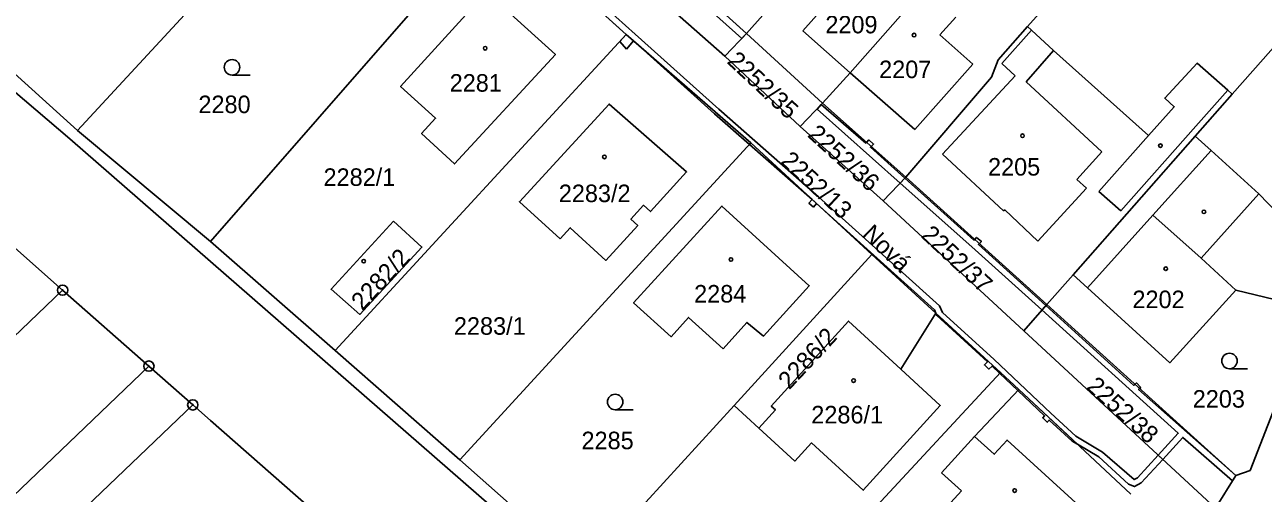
# Model space of a CAD drawing. Extents: x -562167 to -556918, y -1077891 to -1070763.
# Drawn here: x -560763.4 to -560643.5, y -1077711.6 to -1077666.3 of the extents above; entities that cross this region are included whole.
import ezdxf

# ---------------------------------------------------------------- set-up
doc = ezdxf.new("R2010")
doc.units = 0
for name, color, linetype in [('Hranice parcel', 7, 'Continuous'), ('Parcelní čísla', 7, 'Continuous'), ('Pop  PČ popisy', 7, 'Continuous'), ('Vnitřní kresba', 7, 'Continuous'), ('Věcná břemena k části', 7, 'Continuous'), ('Značky bodu BP', 7, 'Continuous'), ('Značky budov', 7, 'Continuous'), ('Značky kultur', 7, 'Continuous')]:
    doc.layers.add(name, color=color, linetype=linetype)

msp = doc.modelspace()

# ---------------------------------------------------------------- linework, layer by layer
at = {"layer": 'Hranice parcel'}
for p, q in [((-560758.33, -1077676.51), (-560729.47, -1077645.24)), ((-560681.37, -1077653.38), (-560693.51, -1077667.11)), ((-560706.25, -1077655.58), (-560693.51, -1077667.11)), ((-560745.45, -1077687.26), (-560717.88, -1077655.72)), ((-560695.64, -1077669.29), (-560708.43, -1077657.94)), ((-560662.13, -1077661.68), (-560666.3, -1077666.42)), ((-560637.71, -1077663.05), (-560646.47, -1077672.98)), ((-560771.17, -1077664.88), (-560758.33, -1077676.51)), ((-560705.17, -1077667.19), (-560733.38, -1077697.8)), ((-560693.1, -1077677.71), (-560705.17, -1077667.19)), ((-560695.64, -1077669.29), (-560693.51, -1077667.11)), ((-560693.51, -1077667.11), (-560686.17, -1077673.87)), ((-560688.32, -1077676.13), (-560695.64, -1077669.29)), ((-560759.77, -1077691.97), (-560783.44, -1077671.09)), ((-560646.47, -1077672.98), (-560650.05, -1077677.04)), ((-560688.32, -1077676.13), (-560686.17, -1077673.87)), ((-560686.17, -1077673.87), (-560678.08, -1077681.02)), ((-560758.33, -1077676.51), (-560745.45, -1077687.26)), ((-560680.29, -1077683.33), (-560688.32, -1077676.13)), ((-560650.05, -1077677.04), (-560661.89, -1077690.47)), ((-560721.29, -1077708.41), (-560693.1, -1077677.71)), ((-560681.4, -1077688.51), (-560693.1, -1077677.71)), ((-560680.29, -1077683.33), (-560678.08, -1077681.02)), ((-560678.08, -1077681.02), (-560664.44, -1077693.36)), ((-560666.67, -1077695.92), (-560680.29, -1077683.33)), ((-560733.38, -1077697.8), (-560745.45, -1077687.26)), ((-560694.73, -1077703.13), (-560681.4, -1077688.51)), ((-560675.19, -1077694.19), (-560681.4, -1077688.51)), ((-560661.89, -1077690.47), (-560664.44, -1077693.36)), ((-560759.77, -1077691.97), (-560803.22, -1077733.49)), ((-560751.42, -1077699.33), (-560759.77, -1077691.97)), ((-560666.67, -1077695.92), (-560664.44, -1077693.36)), ((-560664.44, -1077693.36), (-560646.13, -1077709.94)), ((-560678.59, -1077699.61), (-560675.19, -1077694.19)), ((-560668.91, -1077699.94), (-560675.19, -1077694.19)), ((-560648.1, -1077713.08), (-560666.67, -1077695.92)), ((-560733.38, -1077697.8), (-560721.29, -1077708.41)), ((-560751.42, -1077699.33), (-560795.55, -1077741.52)), ((-560747.16, -1077703.08), (-560751.42, -1077699.33)), ((-560667.14, -1077701.59), (-560668.91, -1077699.94)), ((-560656.3, -1077711.73), (-560667.14, -1077701.59)), ((-560747.16, -1077703.08), (-560791.66, -1077745.59)), ((-560709.24, -1077719.03), (-560694.73, -1077703.13)), ((-560694.73, -1077703.13), (-560692.34, -1077705.33)), ((-560721.29, -1077708.41), (-560709.24, -1077719.03)), ((-560646.13, -1077709.94), (-560648.1, -1077713.08))]:
    msp.add_line(p, q, dxfattribs=at)
for points in [[(-560853.86, -1077598.32), (-560800.15, -1077642.27), (-560759.08, -1077677.32), (-560710.12, -1077719.99), (-560671.25, -1077752.44)], [(-560666.48, -1077651.61), (-560683.47, -1077670.91), (-560686.17, -1077673.87)], [(-560717.88, -1077655.72), (-560717.28, -1077656.26), (-560705.17, -1077667.19)], [(-560718.71, -1077663.08), (-560727.03, -1077672.24), (-560723.65, -1077675.31), (-560725, -1077676.8), (-560721.81, -1077679.74), (-560712.03, -1077669.15), (-560718.71, -1077663.08)], [(-560666.3, -1077666.42), (-560669.15, -1077669.65), (-560669.8, -1077671.32), (-560678.08, -1077681.02)], [(-560646.47, -1077672.98), (-560646.9, -1077672.6), (-560649.86, -1077669.98), (-560653.01, -1077673.36), (-560652.09, -1077674.2), (-560654.57, -1077676.99), (-560663.8, -1077668.76), (-560665.92, -1077666.78), (-560666.3, -1077666.42)], [(-560711.59, -1077687.01), (-560715.52, -1077683.41), (-560706.84, -1077673.95), (-560699.33, -1077680.52), (-560702.84, -1077684.36), (-560703.51, -1077683.75), (-560704.73, -1077685.1), (-560704.06, -1077685.71), (-560707.15, -1077689.09), (-560710.6, -1077685.93), (-560711.59, -1077687.01)], [(-560637.45, -1077689.31), (-560643.9, -1077682.63), (-560648.5, -1077678.45), (-560650.05, -1077677.04)], [(-560695.77, -1077697.64), (-560693.48, -1077695.1), (-560691.88, -1077696.42), (-560687.44, -1077691.55), (-560695.91, -1077683.83), (-560702.77, -1077691.32), (-560704.47, -1077693.21), (-560700.83, -1077696.49), (-560699.13, -1077694.61), (-560695.77, -1077697.64)], [(-560727.71, -1077685.27), (-560724.97, -1077687.79), (-560730.98, -1077694.32), (-560733.76, -1077691.88), (-560727.71, -1077685.27)], [(-560661.89, -1077690.47), (-560660.49, -1077691.75), (-560652.51, -1077699), (-560646.12, -1077691.96), (-560638.63, -1077693.78)], [(-560646.13, -1077709.94), (-560644.74, -1077709.43), (-560638.63, -1077693.78)], [(-560678.59, -1077699.61), (-560683.65, -1077694.97), (-560691.13, -1077703.2), (-560690.73, -1077703.57), (-560692.34, -1077705.33)], [(-560692.34, -1077705.33), (-560688.85, -1077708.53), (-560687.24, -1077706.76), (-560682.21, -1077711.36), (-560674.75, -1077703.14), (-560678.59, -1077699.61)], [(-560685.75, -1077718.33), (-560680.91, -1077712.87), (-560668.91, -1077699.94)], [(-560685.75, -1077718.33), (-560682.84, -1077720.58), (-560678.25, -1077724.84), (-560671.48, -1077717.49), (-560667.08, -1077721.54), (-560660.16, -1077713.91), (-560668.29, -1077706.5), (-560669.53, -1077707.87), (-560671.45, -1077706.13), (-560667.14, -1077701.59)], [(-560680.07, -1077762.65), (-560691.8, -1077751.7), (-560745.45, -1077704.59), (-560747.16, -1077703.08)]]:
    msp.add_lwpolyline(points, dxfattribs=at)
at = {"layer": 'Vnitřní kresba'}
for p, q in [((-560688.06, -1077666.84), (-560681.73, -1077659.74)), ((-560674.8, -1077667.25), (-560673.25, -1077665.52)), ((-560688.06, -1077666.84), (-560683.47, -1077670.91)), ((-560674.8, -1077667.25), (-560671.6, -1077670.09)), ((-560668.78, -1077670), (-560665.92, -1077666.78)), ((-560666.45, -1077671.79), (-560663.8, -1077668.76)), ((-560677.23, -1077676.42), (-560671.6, -1077670.09)), ((-560668.78, -1077670), (-560667.5, -1077671.21)), ((-560683.47, -1077670.91), (-560677.23, -1077676.42)), ((-560674.55, -1077678.8), (-560667.5, -1077671.21)), ((-560666.45, -1077671.79), (-560659.12, -1077678.57)), ((-560650, -1077676.09), (-560646.9, -1077672.6)), ((-560657.28, -1077684.28), (-560650, -1077676.09)), ((-560659.38, -1077682.41), (-560654.57, -1077676.99)), ((-560654.15, -1077684.72), (-560648.5, -1077678.45)), ((-560674.55, -1077678.8), (-560668.62, -1077684.3)), ((-560661.54, -1077681.25), (-560659.12, -1077678.57)), ((-560665.29, -1077687.21), (-560660.6, -1077682.1)), ((-560661.54, -1077681.25), (-560660.6, -1077682.1)), ((-560659.38, -1077682.41), (-560657.28, -1077684.28)), ((-560649.49, -1077688.88), (-560643.9, -1077682.63)), ((-560668.62, -1077684.3), (-560668.51, -1077684.19)), ((-560668.51, -1077684.19), (-560665.29, -1077687.21)), ((-560660.49, -1077691.75), (-560654.15, -1077684.72)), ((-560654.15, -1077684.72), (-560649.49, -1077688.88)), ((-560649.49, -1077688.88), (-560646.12, -1077691.96)), ((-560674.63, -1077709.66), (-560671.45, -1077706.13)), ((-560674.63, -1077709.66), (-560672.71, -1077711.4)), ((-560675.16, -1077714.1), (-560672.71, -1077711.4))]:
    msp.add_line(p, q, dxfattribs=at)
at = {"layer": 'Věcná břemena k části'}
for points in [[(-560706.33, -1077655.67), (-560706.75, -1077656.12), (-560693.98, -1077667.59), (-560693.51, -1077667.11), (-560702.15, -1077659.29), (-560701.95, -1077659.07), (-560702.4, -1077658.67), (-560702.59, -1077658.89), (-560702.64, -1077658.94)], [(-560705.15, -1077668.63), (-560704.47, -1077667.8), (-560705.17, -1077667.19), (-560705.81, -1077667.88)], [(-560693.23, -1077677.85), (-560693.1, -1077677.71), (-560704.47, -1077667.8), (-560696.61, -1077674.88)], [(-560686.69, -1077674.42), (-560678.63, -1077681.59), (-560678.18, -1077681.12), (-560681.52, -1077678.12), (-560681.22, -1077677.81), (-560681.66, -1077677.41), (-560681.9, -1077677.65), (-560681.97, -1077677.72), (-560686.28, -1077673.98)], [(-560687.17, -1077683.18), (-560693.1, -1077677.71), (-560693.23, -1077677.85)], [(-560678.63, -1077681.59), (-560671.69, -1077687.76), (-560664.91, -1077693.89), (-560664.52, -1077693.46), (-560671.06, -1077687.53), (-560670.97, -1077687.45), (-560670.77, -1077687.25), (-560671.23, -1077686.86), (-560671.42, -1077687.05), (-560671.5, -1077687.12), (-560678.18, -1077681.12)], [(-560687.02, -1077683.92), (-560686.73, -1077683.59), (-560687.17, -1077683.18), (-560687.48, -1077683.53)], [(-560664.91, -1077693.89), (-560651.71, -1077705.83), (-560653.65, -1077707.95), (-560653.21, -1077708.36), (-560651.26, -1077706.23), (-560646.44, -1077710.44), (-560646.13, -1077709.94), (-560655.55, -1077701.6), (-560655.45, -1077701.5), (-560655.33, -1077701.39), (-560655.74, -1077700.95), (-560655.9, -1077701.1), (-560656, -1077701.2), (-560664.52, -1077693.46)], [(-560668.99, -1077700.03), (-560668.91, -1077699.94), (-560675.19, -1077694.19), (-560675.1, -1077694.41), (-560670.18, -1077698.91), (-560670.48, -1077699.21), (-560670.04, -1077699.62), (-560669.74, -1077699.32)], [(-560661.46, -1077706.9), (-560667.14, -1077701.59), (-560668.91, -1077699.94), (-560668.99, -1077700.03), (-560667.24, -1077701.69), (-560664.65, -1077704.16), (-560664.83, -1077704.35), (-560664.39, -1077704.76), (-560664.21, -1077704.56), (-560661.97, -1077706.6)]]:
    msp.add_lwpolyline(points, close=True, dxfattribs=at)
msp.add_lwpolyline([(-560711.44, -1077661.53), (-560705.17, -1077667.19), (-560704.47, -1077667.8), (-560693.1, -1077677.71), (-560687.17, -1077683.18), (-560686.73, -1077683.59), (-560675.32, -1077693.86), (-560675.19, -1077694.19), (-560668.91, -1077699.94), (-560667.14, -1077701.59), (-560661.46, -1077706.9), (-560659.38, -1077708.13), (-560656.51, -1077710.75), (-560655.95, -1077710.99), (-560655.28, -1077710.62), (-560653.21, -1077708.36), (-560653.65, -1077707.95), (-560655.66, -1077710.14), (-560655.98, -1077710.32), (-560659.03, -1077707.65), (-560661.61, -1077706.11), (-560664.04, -1077703.9), (-560669.54, -1077698.68), (-560674.54, -1077694.12), (-560674.83, -1077693.5), (-560686.55, -1077682.92), (-560696.22, -1077674.43), (-560704.32, -1077667.17), (-560710.88, -1077661.26)], dxfattribs=at)
at = {"layer": 'Značky bodu BP'}
for centre, radius in [((-560759.77, -1077691.97), 0.5), ((-560759.77, -1077691.97), 0.0303), ((-560751.42, -1077699.33), 0.5), ((-560751.42, -1077699.33), 0.0303), ((-560747.16, -1077703.08), 0.5), ((-560747.16, -1077703.08), 0.0303)]:
    msp.add_circle(centre, radius, dxfattribs=at)
at = {"layer": 'Značky budov'}
for centre in [(-560677.29, -1077667.26), (-560718.84, -1077668.53), (-560666.79, -1077677.01), (-560653.43, -1077677.97), (-560707.29, -1077679.06), (-560649.22, -1077684.38), (-560730.61, -1077689.16), (-560695.03, -1077689), (-560652.91, -1077689.89), (-560683.15, -1077700.73), (-560667.55, -1077711.38)]:
    msp.add_circle(centre, 0.175, dxfattribs=at)
at = {"layer": 'Značky kultur'}
for p, q in [((-560743.36, -1077671.13), (-560741.61, -1077671.13)), ((-560646.74, -1077699.58), (-560644.99, -1077699.58)), ((-560706.25, -1077703.55), (-560704.5, -1077703.55))]:
    msp.add_line(p, q, dxfattribs=at)
for centre in [(-560743.36, -1077670.38), (-560646.74, -1077698.83), (-560706.25, -1077702.8)]:
    msp.add_circle(centre, 0.75, dxfattribs=at)

# ---------------------------------------------------------------- texts
at = {"layer": 'Parcelní čísla'}
for s, p in [('2209', (-560685.89, -1077667.09)), ('2207', (-560680.68, -1077671.43)), ('2281', (-560722.28, -1077672.74)), ('2280', (-560746.62, -1077674.82)), ('2205', (-560670.13, -1077680.87)), ('2282/1', (-560734.5, -1077681.87)), ('2283/2', (-560711.71, -1077683.44)), ('2284', (-560698.6, -1077693.17)), ('2202', (-560656.14, -1077693.71)), ('2283/1', (-560721.87, -1077696.29)), ('2203', (-560650.3, -1077703.35)), ('2286/1', (-560687.25, -1077704.88)), ('2285', (-560709.51, -1077707.38))]:
    msp.add_text(s, height=1.7, dxfattribs=at).set_placement(p)
for s, rotation, p in [('2252/35', 317, (-560695.5, -1077669.91)), ('2252/36', 318, (-560687.71, -1077677.03)), ('2252/13', 317, (-560690.31, -1077679.59)), ('2252/37', 317, (-560676.7, -1077686.77)), ('2282/2', 47, (-560730.74, -1077694.02)), ('2286/2', 47, (-560689.38, -1077701.68)), ('2252/38', 318, (-560660.69, -1077701.45))]:
    msp.add_text(s, height=1.7, rotation=rotation, dxfattribs=at).set_placement(p)
at = {"layer": 'Pop  PČ popisy'}
msp.add_text('Nová', height=1.7, rotation=316, dxfattribs=at).set_placement((-560682.42, -1077686.67))

doc.saveas('drawing.dxf')
